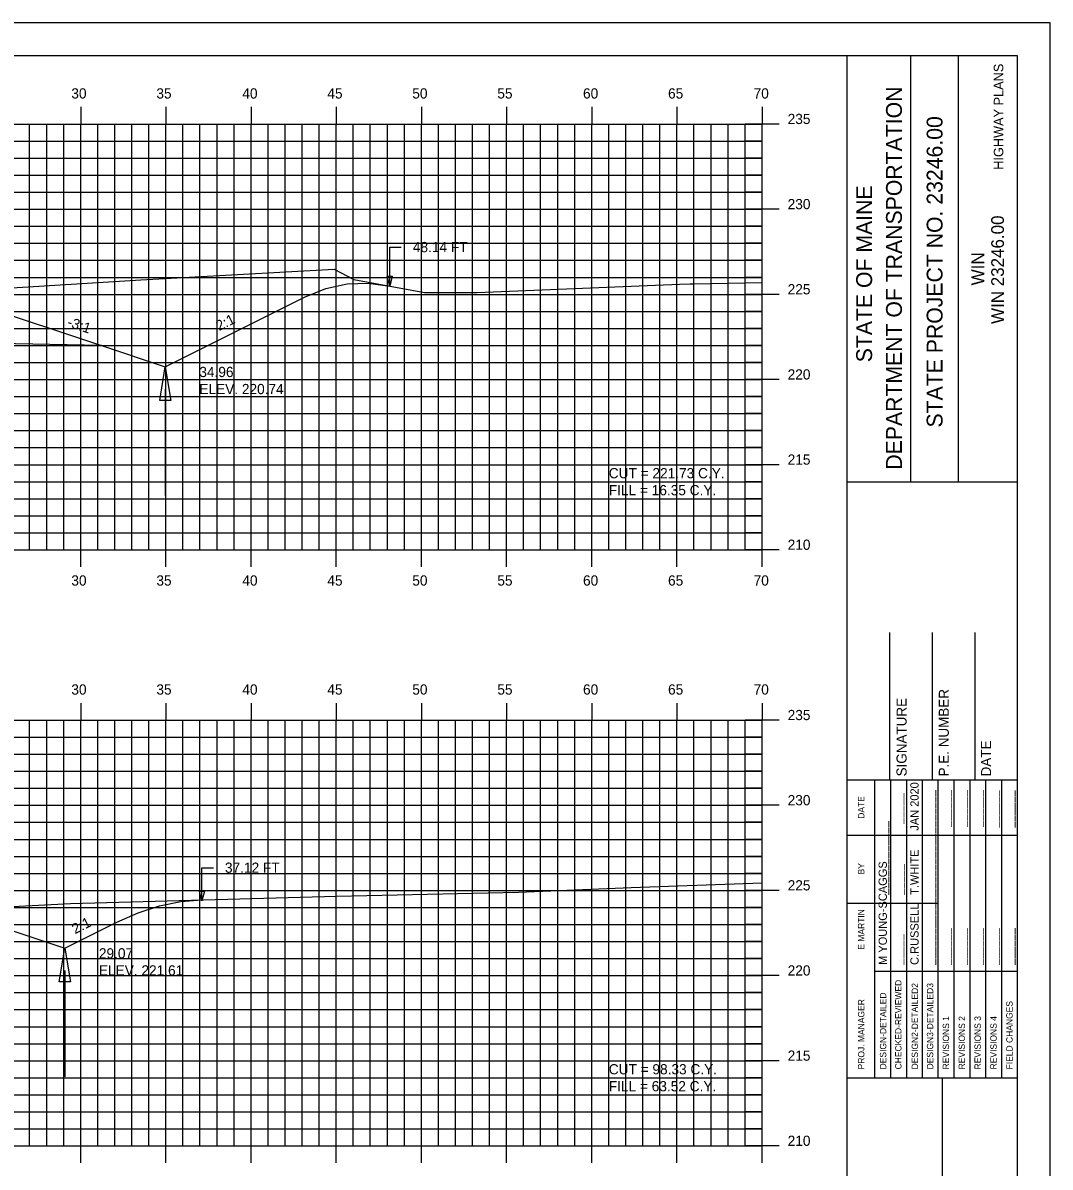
# Model space of a CAD drawing. Extents: x 1137654 to 1137824, y 608981 to 609091.
# Drawn here: x 1137764 to 1137824.3, y 609024.1 to 609091.3 of the extents above; entities that cross this region are included whole.
import ezdxf

# ---------------------------------------------------------------- set-up
doc = ezdxf.new("R2010")
doc.units = 0
for name, color, linetype in [('ANNOTATION', 7, 'Continuous'), ('BORDER', 7, 'Continuous'), ('D_Drainage_Ditch_Line', 7, 'Continuous'), ('D_Roadway_SlopeLines', 7, 'Continuous'), ('D_Roadway_SubGrade', 7, 'Continuous'), ('D_Text_Standard', 7, 'Continuous'), ('H_V ANNOTATION', 7, 'Continuous'), ('HIGHWAY_TITLE', 7, 'Continuous'), ('MAJOR', 7, 'Continuous'), ('MINOR', 7, 'Continuous'), ('PLOT BOUNDARY', 7, 'Continuous'), ('S_Roadway_Centerline', 7, 'Continuous')]:
    doc.layers.add(name, color=color, linetype=linetype)

msp = doc.modelspace()

# ---------------------------------------------------------------- linework, layer by layer
for points in [[(1137703.372, 609073.203), (1137704.622, 609073.195), (1137705.872, 609073.01), (1137707.122, 609072.649), (1137708.372, 609072.113), (1137710.435, 609071.081), (1137714.685, 609072.498), (1137722.408, 609075.072), (1137722.409, 609075.072), (1137726.409, 609075.232), (1137737.409, 609075.452), (1137748.409, 609075.232), (1137761.476, 609074.71), (1137768.621, 609072.328), (1137772.371, 609071.078), (1137780.547, 609075.166), (1137781.797, 609075.675), (1137783.047, 609075.953), (1137784.297, 609075.999), (1137785.547, 609075.814)], [(1137700.848, 609033.177), (1137711.685, 609036.789), (1137714.685, 609037.789), (1137722.408, 609040.363), (1137722.409, 609040.363), (1137726.409, 609040.523), (1137737.409, 609040.743), (1137748.409, 609040.743), (1137755.981, 609040.44), (1137763.476, 609037.942), (1137766.476, 609036.942), (1137769.526, 609038.467), (1137770.776, 609039.018), (1137772.026, 609039.421), (1137773.276, 609039.676), (1137774.526, 609039.784)]]:
    msp.add_lwpolyline(points)
at = {"layer": 'BORDER'}
for p, q in [((1137812.41, 608984.335), (1137812.41, 609089.335)), ((1137816.138, 609064.332), (1137816.138, 609089.332)), ((1137818.933, 609064.332), (1137818.933, 609089.332)), ((1137812.411, 609064.329), (1137822.41, 609064.329)), ((1137814.91, 609046.838), (1137814.91, 609055.485)), ((1137817.41, 609046.838), (1137817.41, 609055.485)), ((1137819.91, 609046.838), (1137819.91, 609055.485)), ((1137812.41, 609046.838), (1137822.41, 609046.838)), ((1137812.41, 609029.338), (1137822.41, 609029.338)), ((1137818.001, 608994.338), (1137818.001, 609029.338))]:
    msp.add_line(p, q, dxfattribs=at)
msp.add_lwpolyline([(1137662.41, 608984.335), (1137822.41, 608984.335), (1137822.41, 609089.335), (1137662.41, 609089.335)], close=True, dxfattribs=at)
for points in [[(1137814.024, 609043.588), (1137814.024, 609046.838)], [(1137814.957, 609029.341), (1137814.957, 609046.838)], [(1137815.889, 609046.838), (1137815.889, 609029.341)], [(1137816.82, 609029.341), (1137816.82, 609046.838)], [(1137817.752, 609029.341), (1137817.752, 609046.838)], [(1137818.684, 609029.341), (1137818.684, 609046.838)], [(1137819.615, 609029.341), (1137819.615, 609046.838)], [(1137820.547, 609029.341), (1137820.547, 609046.838)], [(1137821.479, 609029.341), (1137821.479, 609046.838)], [(1137814.025, 609029.341), (1137814.025, 609046.132)], [(1137812.41, 609043.588), (1137822.41, 609043.588)], [(1137812.41, 609039.588), (1137814.025, 609039.588)], [(1137814.024, 609039.588), (1137817.751, 609039.588)], [(1137814.024, 609035.588), (1137822.41, 609035.588)]]:
    msp.add_lwpolyline(points, dxfattribs=at)
at = {"layer": 'D_Drainage_Ditch_Line'}
for p, q in [((1137772.371, 609069.766), (1137772.37, 609063.522)), ((1137766.476, 609035.63), (1137766.476, 609029.386))]:
    msp.add_line(p, q, dxfattribs=at)
for points in [[(1137772.699, 609069.109), (1137772.043, 609069.109), (1137772.371, 609071.078)], [(1137766.804, 609034.973), (1137766.148, 609034.973), (1137766.476, 609036.942)]]:
    msp.add_lwpolyline(points, close=True, dxfattribs=at)
at = {"layer": 'D_Roadway_SlopeLines'}
for points in [[(1137772.371, 609071.078), (1137780.547, 609075.166), (1137781.797, 609075.675), (1137783.047, 609075.953), (1137784.297, 609075.999), (1137785.547, 609075.814)], [(1137768.621, 609072.328), (1137772.371, 609071.078)], [(1137766.476, 609036.942), (1137769.526, 609038.467), (1137770.776, 609039.018), (1137772.026, 609039.421), (1137773.276, 609039.676), (1137774.526, 609039.784)], [(1137763.476, 609037.942), (1137766.476, 609036.942)]]:
    msp.add_lwpolyline(points, dxfattribs=at)
at = {"layer": 'D_Roadway_SubGrade'}
msp.add_lwpolyline([(1137748.409, 609074.816), (1137748.409, 609074.982), (1137761.476, 609074.46), (1137761.476, 609074.71), (1137761.476, 609074.71), (1137768.621, 609072.328), (1137748.409, 609072.732)], close=True, dxfattribs=at)
at = {"layer": 'D_Text_Standard'}
for points in [[(1137785.547, 609075.821), (1137785.547, 609078.113), (1137786.227, 609078.113)], [(1137774.526, 609039.717), (1137774.517, 609041.671), (1137775.197, 609041.671)]]:
    msp.add_lwpolyline(points, dxfattribs=at)
for points in [[(1137785.547, 609075.821), (1137785.401, 609076.403), (1137785.692, 609076.403)], [(1137774.526, 609039.717), (1137774.378, 609040.298), (1137774.669, 609040.3)]]:
    msp.add_lwpolyline(points, close=True, dxfattribs=at)
at = {"layer": 'MAJOR'}
for p, q in [((1137767.409, 609086.337), (1137767.409, 609085.335)), ((1137772.409, 609086.337), (1137772.409, 609085.335)), ((1137777.409, 609086.337), (1137777.409, 609085.335)), ((1137782.409, 609086.337), (1137782.409, 609085.335)), ((1137787.409, 609086.337), (1137787.409, 609085.335)), ((1137792.409, 609086.337), (1137792.409, 609085.335)), ((1137797.409, 609086.337), (1137797.409, 609085.335)), ((1137802.409, 609086.337), (1137802.409, 609085.335)), ((1137807.409, 609086.337), (1137807.409, 609085.335)), ((1137667.409, 609085.335), (1137807.409, 609085.335)), ((1137667.409, 609085.335), (1137807.409, 609085.335)), ((1137767.409, 609060.335), (1137767.409, 609085.335)), ((1137772.409, 609060.335), (1137772.409, 609085.335)), ((1137777.409, 609060.335), (1137777.409, 609085.335)), ((1137782.409, 609060.335), (1137782.409, 609085.335)), ((1137787.409, 609060.335), (1137787.409, 609085.335)), ((1137792.409, 609060.335), (1137792.409, 609085.335)), ((1137797.409, 609060.335), (1137797.409, 609085.335)), ((1137802.409, 609060.335), (1137802.409, 609085.335)), ((1137808.411, 609085.335), (1137806.407, 609085.335)), ((1137807.409, 609060.335), (1137807.409, 609085.335)), ((1137807.409, 609060.335), (1137807.409, 609085.335)), ((1137667.409, 609080.335), (1137807.409, 609080.335)), ((1137808.411, 609080.335), (1137806.407, 609080.335)), ((1137667.409, 609075.335), (1137807.409, 609075.335)), ((1137808.411, 609075.335), (1137806.407, 609075.335)), ((1137667.409, 609070.335), (1137807.409, 609070.335)), ((1137808.411, 609070.335), (1137806.407, 609070.335)), ((1137667.409, 609065.335), (1137807.409, 609065.335)), ((1137808.411, 609065.335), (1137806.407, 609065.335)), ((1137667.409, 609060.335), (1137807.409, 609060.335)), ((1137667.409, 609060.335), (1137807.409, 609060.335)), ((1137767.409, 609059.333), (1137767.409, 609060.335)), ((1137772.409, 609059.333), (1137772.409, 609060.335)), ((1137777.409, 609059.333), (1137777.409, 609060.335)), ((1137782.409, 609059.333), (1137782.409, 609060.335)), ((1137787.409, 609059.333), (1137787.409, 609060.335)), ((1137792.409, 609059.333), (1137792.409, 609060.335)), ((1137797.409, 609059.333), (1137797.409, 609060.335)), ((1137802.409, 609059.333), (1137802.409, 609060.335)), ((1137808.411, 609060.335), (1137806.407, 609060.335)), ((1137807.409, 609059.333), (1137807.409, 609060.335)), ((1137767.409, 609051.337), (1137767.409, 609050.335)), ((1137772.409, 609051.337), (1137772.409, 609050.335)), ((1137777.409, 609051.337), (1137777.409, 609050.335)), ((1137782.409, 609051.337), (1137782.409, 609050.335)), ((1137787.409, 609051.337), (1137787.409, 609050.335)), ((1137792.409, 609051.337), (1137792.409, 609050.335)), ((1137797.409, 609051.337), (1137797.409, 609050.335)), ((1137802.409, 609051.337), (1137802.409, 609050.335)), ((1137807.409, 609051.337), (1137807.409, 609050.335)), ((1137667.409, 609050.335), (1137807.409, 609050.335)), ((1137667.409, 609050.335), (1137807.409, 609050.335)), ((1137767.409, 609025.335), (1137767.409, 609050.335)), ((1137772.409, 609025.335), (1137772.409, 609050.335)), ((1137777.409, 609025.335), (1137777.409, 609050.335)), ((1137782.409, 609025.335), (1137782.409, 609050.335)), ((1137787.409, 609025.335), (1137787.409, 609050.335)), ((1137792.409, 609025.335), (1137792.409, 609050.335)), ((1137797.409, 609025.335), (1137797.409, 609050.335)), ((1137802.409, 609025.335), (1137802.409, 609050.335)), ((1137808.411, 609050.335), (1137806.407, 609050.335)), ((1137807.409, 609025.335), (1137807.409, 609050.335)), ((1137807.409, 609025.335), (1137807.409, 609050.335)), ((1137667.409, 609045.335), (1137807.409, 609045.335)), ((1137808.411, 609045.335), (1137806.407, 609045.335)), ((1137667.409, 609040.335), (1137807.409, 609040.335)), ((1137808.411, 609040.335), (1137806.407, 609040.335)), ((1137667.409, 609035.335), (1137807.409, 609035.335)), ((1137808.411, 609035.335), (1137806.407, 609035.335)), ((1137667.409, 609030.335), (1137807.409, 609030.335)), ((1137808.411, 609030.335), (1137806.407, 609030.335)), ((1137667.409, 609025.335), (1137807.409, 609025.335)), ((1137667.409, 609025.335), (1137807.409, 609025.335)), ((1137767.409, 609024.333), (1137767.409, 609025.335)), ((1137772.409, 609024.333), (1137772.409, 609025.335)), ((1137777.409, 609024.333), (1137777.409, 609025.335)), ((1137782.409, 609024.333), (1137782.409, 609025.335)), ((1137787.409, 609024.333), (1137787.409, 609025.335)), ((1137792.409, 609024.333), (1137792.409, 609025.335)), ((1137797.409, 609024.333), (1137797.409, 609025.335)), ((1137802.409, 609024.333), (1137802.409, 609025.335)), ((1137808.411, 609025.335), (1137806.407, 609025.335)), ((1137807.409, 609024.333), (1137807.409, 609025.335))]:
    msp.add_line(p, q, dxfattribs=at)
at = {"layer": 'MINOR'}
for p, q in [((1137764.409, 609060.335), (1137764.409, 609085.335)), ((1137765.409, 609060.335), (1137765.409, 609085.335)), ((1137766.409, 609060.335), (1137766.409, 609085.335)), ((1137768.409, 609060.335), (1137768.409, 609085.335)), ((1137769.409, 609060.335), (1137769.409, 609085.335)), ((1137770.409, 609060.335), (1137770.409, 609085.335)), ((1137771.409, 609060.335), (1137771.409, 609085.335)), ((1137773.409, 609060.335), (1137773.409, 609085.335)), ((1137774.409, 609060.335), (1137774.409, 609085.335)), ((1137775.409, 609060.335), (1137775.409, 609085.335)), ((1137776.409, 609060.335), (1137776.409, 609085.335)), ((1137778.409, 609060.335), (1137778.409, 609085.335)), ((1137779.409, 609060.335), (1137779.409, 609085.335)), ((1137780.409, 609060.335), (1137780.409, 609085.335)), ((1137781.409, 609060.335), (1137781.409, 609085.335)), ((1137783.409, 609060.335), (1137783.409, 609085.335)), ((1137784.409, 609060.335), (1137784.409, 609085.335)), ((1137785.409, 609060.335), (1137785.409, 609085.335)), ((1137786.409, 609060.335), (1137786.409, 609085.335)), ((1137788.409, 609060.335), (1137788.409, 609085.335)), ((1137789.409, 609060.335), (1137789.409, 609085.335)), ((1137790.409, 609060.335), (1137790.409, 609085.335)), ((1137791.409, 609060.335), (1137791.409, 609085.335)), ((1137793.409, 609060.335), (1137793.409, 609085.335)), ((1137794.409, 609060.335), (1137794.409, 609085.335)), ((1137795.409, 609060.335), (1137795.409, 609085.335)), ((1137796.409, 609060.335), (1137796.409, 609085.335)), ((1137798.409, 609060.335), (1137798.409, 609085.335)), ((1137799.409, 609060.335), (1137799.409, 609085.335)), ((1137800.409, 609060.335), (1137800.409, 609085.335)), ((1137801.409, 609060.335), (1137801.409, 609085.335)), ((1137803.409, 609060.335), (1137803.409, 609085.335)), ((1137804.409, 609060.335), (1137804.409, 609085.335)), ((1137805.409, 609060.335), (1137805.409, 609085.335)), ((1137806.409, 609060.335), (1137806.409, 609085.335)), ((1137667.409, 609084.335), (1137807.409, 609084.335)), ((1137807.409, 609084.335), (1137806.407, 609084.335)), ((1137667.409, 609083.335), (1137807.409, 609083.335)), ((1137807.409, 609083.335), (1137806.407, 609083.335)), ((1137667.409, 609082.335), (1137807.409, 609082.335)), ((1137807.409, 609082.335), (1137806.407, 609082.335)), ((1137667.409, 609081.335), (1137807.409, 609081.335)), ((1137807.409, 609081.335), (1137806.407, 609081.335)), ((1137667.409, 609079.335), (1137807.409, 609079.335)), ((1137807.409, 609079.335), (1137806.407, 609079.335)), ((1137667.409, 609078.335), (1137807.409, 609078.335)), ((1137807.409, 609078.335), (1137806.407, 609078.335)), ((1137667.409, 609077.335), (1137807.409, 609077.335)), ((1137807.409, 609077.335), (1137806.407, 609077.335)), ((1137667.409, 609076.335), (1137807.409, 609076.335)), ((1137807.409, 609076.335), (1137806.407, 609076.335)), ((1137667.409, 609074.335), (1137807.409, 609074.335)), ((1137807.409, 609074.335), (1137806.407, 609074.335)), ((1137667.409, 609073.335), (1137807.409, 609073.335)), ((1137807.409, 609073.335), (1137806.407, 609073.335)), ((1137667.409, 609072.335), (1137807.409, 609072.335)), ((1137807.409, 609072.335), (1137806.407, 609072.335)), ((1137667.409, 609071.335), (1137807.409, 609071.335)), ((1137807.409, 609071.335), (1137806.407, 609071.335)), ((1137667.409, 609069.335), (1137807.409, 609069.335)), ((1137807.409, 609069.335), (1137806.407, 609069.335)), ((1137667.409, 609068.335), (1137807.409, 609068.335)), ((1137807.409, 609068.335), (1137806.407, 609068.335)), ((1137667.409, 609067.335), (1137807.409, 609067.335)), ((1137807.409, 609067.335), (1137806.407, 609067.335)), ((1137667.409, 609066.335), (1137807.409, 609066.335)), ((1137807.409, 609066.335), (1137806.407, 609066.335)), ((1137667.409, 609064.335), (1137807.409, 609064.335)), ((1137807.409, 609064.335), (1137806.407, 609064.335)), ((1137667.409, 609063.335), (1137807.409, 609063.335)), ((1137807.409, 609063.335), (1137806.407, 609063.335)), ((1137667.409, 609062.335), (1137807.409, 609062.335)), ((1137807.409, 609062.335), (1137806.407, 609062.335)), ((1137667.409, 609061.335), (1137807.409, 609061.335)), ((1137807.409, 609061.335), (1137806.407, 609061.335)), ((1137764.409, 609025.335), (1137764.409, 609050.335)), ((1137765.409, 609025.335), (1137765.409, 609050.335)), ((1137766.409, 609025.335), (1137766.409, 609050.335)), ((1137768.409, 609025.335), (1137768.409, 609050.335)), ((1137769.409, 609025.335), (1137769.409, 609050.335)), ((1137770.409, 609025.335), (1137770.409, 609050.335)), ((1137771.409, 609025.335), (1137771.409, 609050.335)), ((1137773.409, 609025.335), (1137773.409, 609050.335)), ((1137774.409, 609025.335), (1137774.409, 609050.335)), ((1137775.409, 609025.335), (1137775.409, 609050.335)), ((1137776.409, 609025.335), (1137776.409, 609050.335)), ((1137778.409, 609025.335), (1137778.409, 609050.335)), ((1137779.409, 609025.335), (1137779.409, 609050.335)), ((1137780.409, 609025.335), (1137780.409, 609050.335)), ((1137781.409, 609025.335), (1137781.409, 609050.335)), ((1137783.409, 609025.335), (1137783.409, 609050.335)), ((1137784.409, 609025.335), (1137784.409, 609050.335)), ((1137785.409, 609025.335), (1137785.409, 609050.335)), ((1137786.409, 609025.335), (1137786.409, 609050.335)), ((1137788.409, 609025.335), (1137788.409, 609050.335)), ((1137789.409, 609025.335), (1137789.409, 609050.335)), ((1137790.409, 609025.335), (1137790.409, 609050.335)), ((1137791.409, 609025.335), (1137791.409, 609050.335)), ((1137793.409, 609025.335), (1137793.409, 609050.335)), ((1137794.409, 609025.335), (1137794.409, 609050.335)), ((1137795.409, 609025.335), (1137795.409, 609050.335)), ((1137796.409, 609025.335), (1137796.409, 609050.335)), ((1137798.409, 609025.335), (1137798.409, 609050.335)), ((1137799.409, 609025.335), (1137799.409, 609050.335)), ((1137800.409, 609025.335), (1137800.409, 609050.335)), ((1137801.409, 609025.335), (1137801.409, 609050.335)), ((1137803.409, 609025.335), (1137803.409, 609050.335)), ((1137804.409, 609025.335), (1137804.409, 609050.335)), ((1137805.409, 609025.335), (1137805.409, 609050.335)), ((1137806.409, 609025.335), (1137806.409, 609050.335)), ((1137667.409, 609049.335), (1137807.409, 609049.335)), ((1137807.409, 609049.335), (1137806.407, 609049.335)), ((1137667.409, 609048.335), (1137807.409, 609048.335)), ((1137807.409, 609048.335), (1137806.407, 609048.335)), ((1137667.409, 609047.335), (1137807.409, 609047.335)), ((1137807.409, 609047.335), (1137806.407, 609047.335)), ((1137667.409, 609046.335), (1137807.409, 609046.335)), ((1137807.409, 609046.335), (1137806.407, 609046.335)), ((1137667.409, 609044.335), (1137807.409, 609044.335)), ((1137807.409, 609044.335), (1137806.407, 609044.335)), ((1137667.409, 609043.335), (1137807.409, 609043.335)), ((1137807.409, 609043.335), (1137806.407, 609043.335)), ((1137667.409, 609042.335), (1137807.409, 609042.335)), ((1137807.409, 609042.335), (1137806.407, 609042.335)), ((1137667.409, 609041.335), (1137807.409, 609041.335)), ((1137807.409, 609041.335), (1137806.407, 609041.335)), ((1137667.409, 609039.335), (1137807.409, 609039.335)), ((1137807.409, 609039.335), (1137806.407, 609039.335)), ((1137667.409, 609038.335), (1137807.409, 609038.335)), ((1137807.409, 609038.335), (1137806.407, 609038.335)), ((1137667.409, 609037.335), (1137807.409, 609037.335)), ((1137807.409, 609037.335), (1137806.407, 609037.335)), ((1137667.409, 609036.335), (1137807.409, 609036.335)), ((1137807.409, 609036.335), (1137806.407, 609036.335)), ((1137667.409, 609034.335), (1137807.409, 609034.335)), ((1137807.409, 609034.335), (1137806.407, 609034.335)), ((1137667.409, 609033.335), (1137807.409, 609033.335)), ((1137807.409, 609033.335), (1137806.407, 609033.335)), ((1137667.409, 609032.335), (1137807.409, 609032.335)), ((1137807.409, 609032.335), (1137806.407, 609032.335)), ((1137667.409, 609031.335), (1137807.409, 609031.335)), ((1137807.409, 609031.335), (1137806.407, 609031.335)), ((1137667.409, 609029.335), (1137807.409, 609029.335)), ((1137807.409, 609029.335), (1137806.407, 609029.335)), ((1137667.409, 609028.335), (1137807.409, 609028.335)), ((1137807.409, 609028.335), (1137806.407, 609028.335)), ((1137667.409, 609027.335), (1137807.409, 609027.335)), ((1137807.409, 609027.335), (1137806.407, 609027.335)), ((1137667.409, 609026.335), (1137807.409, 609026.335)), ((1137807.409, 609026.335), (1137806.407, 609026.335))]:
    msp.add_line(p, q, dxfattribs=at)
at = {"layer": 'PLOT BOUNDARY'}
msp.add_lwpolyline([(1137654.316, 608981.276), (1137824.316, 608981.276), (1137824.316, 609091.276), (1137654.316, 609091.276)], close=True, dxfattribs=at)
at = {"layer": 'S_Roadway_Centerline'}
for points in [[(1137759.89, 609075.513), (1137770.942, 609076.182), (1137782.294, 609076.817), (1137783.443, 609076.205), (1137787.585, 609075.436), (1137790.679, 609075.454), (1137802.587, 609075.931), (1137803.179, 609075.948), (1137803.343, 609075.952), (1137807.409, 609076.022)], [(1137667.409, 609031.673), (1137680.898, 609032.377), (1137683.689, 609032.524), (1137701.957, 609033.219), (1137704.697, 609033.873), (1137715.818, 609036.339), (1137722.54, 609039.054), (1137724.51, 609039.355), (1137725.115, 609039.434), (1137727.86, 609039.504), (1137736.081, 609039.689), (1137744.308, 609039.789), (1137746.709, 609039.808), (1137746.997, 609039.677), (1137753.261, 609039.323), (1137761.612, 609039.363), (1137761.894, 609039.317), (1137766.806, 609039.577), (1137782.426, 609039.995), (1137793.11, 609040.238), (1137799.729, 609040.508), (1137807.409, 609040.788)]]:
    msp.add_lwpolyline(points, dxfattribs=at)

# ---------------------------------------------------------------- texts
at = {"layer": 'ANNOTATION'}
for s, rotation, p in [('-3:1', 341.56521, (1137766.573, 609073.465)), ('2:1', 26.56505, (1137775.531, 609073.176)), ('2:1', 26.56505, (1137767.074, 609037.759))]:
    msp.add_text(s, height=0.6, rotation=rotation, dxfattribs=at).set_placement(p)
at = {"layer": 'BORDER'}
for s, height, p in [('DEPARTMENT OF TRANSPORTATION', 0.93176, (1137815.616, 609065.041)), ('STATE PROJECT NO. 23246.00', 0.93176, (1137818.002, 609067.517)), ('STATE OF MAINE', 0.93176, (1137813.865, 609071.347)), ('WIN 23246.00', 0.74527, (1137821.605, 609073.596)), ('WIN', 0.7453, (1137820.446, 609075.865)), ('P.E. NUMBER', 0.59055, (1137818.37, 609047.03)), ('SIGNATURE', 0.5906, (1137815.89, 609047.03)), ('DATE', 0.5906, (1137820.851, 609047.03)), ('JAN 2020', 0.4845, (1137816.596, 609043.843)), ('DATE', 0.3714, (1137813.414, 609044.544)), ('_____', 0.4845, (1137815.627, 609044.243)), ('______', 0.4845, (1137817.49, 609044.063)), ('______', 0.4845, (1137818.422, 609044.065)), ('______', 0.4845, (1137819.354, 609044.067)), ('______', 0.4845, (1137820.285, 609044.067)), ('______', 0.4845, (1137821.217, 609044.036)), ('______', 0.4845, (1137822.149, 609044.036)), ('____________', 0.48455, (1137814.733, 609040.073)), ('____________', 0.48455, (1137817.49, 609040.073)), ('T.WHITE', 0.4845, (1137816.596, 609040.073)), ('BY', 0.3714, (1137813.414, 609041.273)), ('M YOUNG-SCAGGS', 0.48455, (1137814.733, 609035.961)), ('_____', 0.4845, (1137815.664, 609040.073)), ('____________', 0.48455, (1137817.49, 609035.961)), ('E MARTIN', 0.3727, (1137813.414, 609036.855)), ('C.RUSSELL', 0.4845, (1137816.596, 609035.961)), ('_____', 0.4845, (1137815.627, 609035.961)), ('______', 0.4845, (1137818.422, 609035.961)), ('______', 0.4845, (1137819.354, 609035.961)), ('______', 0.4845, (1137820.285, 609035.961)), ('______', 0.4845, (1137821.217, 609035.961)), ('______', 0.4845, (1137822.149, 609035.961)), ('CHECKED-REVIEWED', 0.37275, (1137815.591, 609029.826)), ('DESIGN2-DETAILED2', 0.37275, (1137816.56, 609029.826)), ('DESIGN3-DETAILED3', 0.37275, (1137817.454, 609029.826)), ('DESIGN-DETAILED', 0.37275, (1137814.696, 609029.826)), ('PROJ. MANAGER', 0.37275, (1137813.414, 609029.826)), ('FIELD CHANGES', 0.37275, (1137822.112, 609029.826)), ('REVISIONS 1', 0.37275, (1137818.386, 609029.826)), ('REVISIONS 2', 0.37275, (1137819.317, 609029.826)), ('REVISIONS 3', 0.37275, (1137820.249, 609029.826)), ('REVISIONS 4', 0.37275, (1137821.181, 609029.826))]:
    msp.add_text(s, height=height, rotation=90, dxfattribs=at).set_placement(p)
at = {"layer": 'D_Text_Standard'}
for s, p in [('48.14 FT', (1137786.907, 609077.813)), ('34.96', (1137774.371, 609070.478)), ('ELEV. 220.74', (1137774.371, 609069.476)), ('CUT = 221.73 C.Y.', (1137798.409, 609064.535)), ('FILL = 16.35 C.Y.', (1137798.409, 609063.539)), ('37.12 FT', (1137775.877, 609041.371)), ('29.07', (1137768.476, 609036.342)), ('ELEV. 221.61', (1137768.476, 609035.34)), ('CUT = 98.33 C.Y.', (1137798.409, 609029.535)), ('FILL = 63.52 C.Y.', (1137798.409, 609028.539))]:
    msp.add_text(s, height=0.6, dxfattribs=at).set_placement(p)
at = {"layer": 'H_V ANNOTATION'}
for s, p in [('30', (1137766.858, 609086.835)), ('35', (1137771.85, 609086.835)), ('40', (1137776.896, 609086.835)), ('45', (1137781.888, 609086.835)), ('50', (1137786.874, 609086.835)), ('55', (1137791.866, 609086.835)), ('60', (1137796.896, 609086.835)), ('65', (1137801.888, 609086.835)), ('70', (1137806.911, 609086.835)), ('235', (1137808.909, 609085.335)), ('230', (1137808.909, 609080.335)), ('225', (1137808.909, 609075.335)), ('220', (1137808.909, 609070.335)), ('215', (1137808.909, 609065.335)), ('210', (1137808.909, 609060.335)), ('30', (1137766.858, 609058.235)), ('35', (1137771.85, 609058.235)), ('40', (1137776.896, 609058.235)), ('45', (1137781.888, 609058.235)), ('50', (1137786.874, 609058.235)), ('55', (1137791.866, 609058.235)), ('60', (1137796.896, 609058.235)), ('65', (1137801.888, 609058.235)), ('70', (1137806.911, 609058.235)), ('30', (1137766.858, 609051.835)), ('35', (1137771.85, 609051.835)), ('40', (1137776.896, 609051.835)), ('45', (1137781.888, 609051.835)), ('50', (1137786.874, 609051.835)), ('55', (1137791.866, 609051.835)), ('60', (1137796.896, 609051.835)), ('65', (1137801.888, 609051.835)), ('70', (1137806.911, 609051.835)), ('235', (1137808.909, 609050.335)), ('230', (1137808.909, 609045.335)), ('225', (1137808.909, 609040.335)), ('220', (1137808.909, 609035.335)), ('215', (1137808.909, 609030.335)), ('210', (1137808.909, 609025.335))]:
    msp.add_text(s, height=0.6, dxfattribs=at).set_placement(p)
at = {"layer": 'HIGHWAY_TITLE'}
msp.add_text('HIGHWAY PLANS', height=0.55901, rotation=90, dxfattribs=at).set_placement((1137821.568, 609082.65))

doc.saveas('drawing.dxf')
